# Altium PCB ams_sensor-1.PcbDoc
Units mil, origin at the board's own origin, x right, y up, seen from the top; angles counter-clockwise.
Board outline 420 x 130 mil, 2 copper layers (Top Layer, Bottom Layer), stack 64.8 mil thick; 2 components, 4 nets, 13 pads, 4 vias.
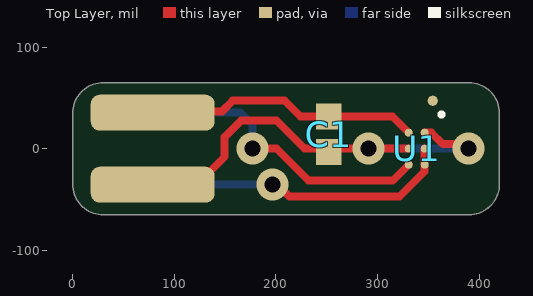
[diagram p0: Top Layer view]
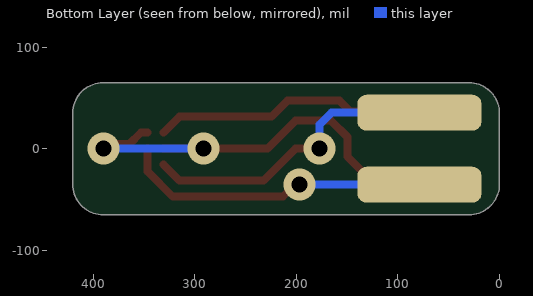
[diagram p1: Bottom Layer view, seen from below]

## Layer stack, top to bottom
Top Solder: solder mask 0.5906, Solder Resist, Dk 3.5
Top Layer: signal copper 1.4
Dielectric 1: dielectric 62, FR-4, Dk 4.8
Bottom Layer: signal copper 1.4
Bottom Solder: solder mask 0.5906, Solder Resist, Dk 3.5

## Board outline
0,-34.96 0,34.96 cw(c30,34.96) 30,64.96 390,65 cw(c389.98,34.98) 420,34.96 420,-34.96 cw(c390,-34.96) 390,-64.96 30,-65 cw(c30.02,-34.98)

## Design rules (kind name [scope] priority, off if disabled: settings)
Clearance [All] p1: gap=7.87 ignorepadtopadclearanceinfootprint=FALSE except(0: Arc-Hole Track-Hole SMDPad-Hole THPad-Hole Via-Hole Fill-Hole Poly-Hole Region-Hole Text-Hole)
MinimumSolderMaskSliver [All] p1: minsoldermaskwidth=3.94
PolygonConnect [All] p1: connectstyle=Relief reliefconductorwidth=10 reliefentries=4 polygonreliefangle="90 Angle" airgapwidth=10
RoutingVias [All] p1: holewidth=11 width=31 viastyle="Through Hole" minholewidth=15 minwidth=31 maxholewidth=28 maxwidth=50
SolderMaskExpansion [All] p1: expansion=2 istentingtop=FALSE
Width [All] p1: maxlimit=10 minlimit=7.87 preferedwidth=7.99
29 further rules are at their usual default settings.

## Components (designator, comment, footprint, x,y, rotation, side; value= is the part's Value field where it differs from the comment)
C1 "10V X7R 0402" CAPC1005X55[0402] 251.97,14.17 r270 top value=1E-7
U1 "AMS_AS621x" AMS_BGA6C40P3X2_150X102X60 338.58,0 r270 top

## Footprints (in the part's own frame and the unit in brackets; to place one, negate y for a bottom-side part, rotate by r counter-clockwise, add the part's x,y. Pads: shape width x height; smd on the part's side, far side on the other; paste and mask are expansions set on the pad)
AMS_BGA6C40P3X2_150X102X60 [mm] "BGA, 6-Leads, Body 1.50x1.02mmx0.60mm, Pitch 0.40mm"
  round 0.2 smd mask+0.049: A1(-0.4,0.2) A2(0,0.2) A3(0.4,0.2) B1(-0.4,-0.2) B2(0,-0.2) B3(0.4,-0.2)
  silkscreen extent -0.9,0.57 -0.81,0.67, body extent -0.75,-0.52 0.75,0.52, height 0.6
CAPC1005X55[0402] [mm]
  rect 0.65x0.63 smd mask+0.064: 1(-0.44,0) 2(0.44,0)
  body extent -0.5,-0.25 0.5,0.25, height 0.55

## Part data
C1: library part CAP-00140, "0.1µF ±10% 10V Ceramic Capacitor X7R 0402 (1005 Metric)", manufacturer="Samsung Electro-Mechanics America, Inc.", manufacturer_pn=CL05B104KP5NNNC, Supplier Part Number 1=1276-1002-1-ND, value_text=0.1u
U1: library part ICANA-00040, "TEMP SENSOR WLCSP6 I2C", manufacturer=AMS, manufacturer_pn=AS6212-AWLT-S, Supplier Part Number 1=961-AS6212-AWLT-SCT-ND

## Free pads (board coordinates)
  rrect50% 122.05x35.43 smd paste-196.85 mask-5.91: 1(78.74,35.43) 2(78.74,-35.43)
  rrect50% 122.05x35.43 smd far side paste-196.85 mask-5.91: 3(78.74,35.43) 4(78.74,-35.43)
  round 10 smd paste-5: 5(354.33,47.24)

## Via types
v1: diameter 31.5, hole 15.75, Top Layer to Bottom Layer, tented both sides, 4 vias

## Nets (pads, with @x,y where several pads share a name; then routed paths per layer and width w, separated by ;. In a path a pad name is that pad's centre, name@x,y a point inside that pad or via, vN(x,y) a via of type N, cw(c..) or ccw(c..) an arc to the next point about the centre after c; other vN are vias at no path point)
GND: C1.2 pad.2 U1.A1 U1.B2 | length 449
  Top Layer w7.87: pad.2 122.05,-35.43 149.61,-7.87 149.61,11.42 165.75,27.56 200.79,27.56 228.35,0 v1(291.34,0) U1.B2 ; U1.A1 352.98,15.75 364.21,4.52 385.24,4.52 v1(389.76,0)
  Bottom Layer w7.87: v1(291.34,0) v1(389.76,0)
PWR: C1.1 pad.1 U1.B1 | length 269.9
  Top Layer w7.87: pad.1 80.03,36.73 146.96,36.73 157.48,47.24 208.66,47.24 224.41,31.5 C1.1 283.46,31.5 314.96,31.5 U1.B1
SCL: pad.4 U1.A2 U1.A3 | length 305
  Top Layer w7.87: v1(196.85,-35.43) 201.46,-35.43 213.27,-47.24 321.48,-47.24 346.46,-22.27 U1.A3 U1.A2
  Bottom Layer w7.87: pad.4@78.93,-35.43 v1(196.85,-35.43)
SDA: pad.3 U1.B3 | length 300.1
  Top Layer w7.87: v1(177.17,0) 200.79,0 232.28,-31.5 314.96,-31.5 U1.B3
  Bottom Layer w7.87: pad.3@78.77,35.46 165.32,35.46 177.17,23.62 v1(177.17,0)

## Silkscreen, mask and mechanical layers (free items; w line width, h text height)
Board Shape:
  the board outline again, w3.94
scratchpad:
  lines w3.94: 0,-55 0,-65 10,-65
  text "Licensed under" at 5.84,-126.1 h50
  text "CERN-OHL-P v2" at -3.94,-196.85 h50
  text "Source package at" at 1.97,-271.65 h50
  text "https://docs.2to8.cc" at 1.97,-350.39 h50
